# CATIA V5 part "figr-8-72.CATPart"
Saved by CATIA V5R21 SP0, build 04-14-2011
Part number: Part1
Bounding box of the stored display mesh (mm): x -81.893 to 81.893, y -175.508 to 175.508, z -50 to 146
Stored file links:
  D:\CATIA V5R21 E-RESOURCES\CATIA-V5R21\catia-v5r21-prt\c08-catia-v5r20-prt\c08-catia-v5r21-figr-8-72.CATPart
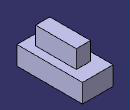
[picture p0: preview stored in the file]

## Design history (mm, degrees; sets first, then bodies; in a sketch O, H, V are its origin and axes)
Body1 (main body)
  Sketch1 on xy-plane, origin (0, 0, 0), H (1, 0, 0), V (0, 1, 0)
    line L1 (-81.8929, 175.5076) -> (81.8929, 175.5076)
    line L2 (81.8929, 175.5076) -> (81.8929, -175.5076)
    line L3 (81.8929, -175.5076) -> (-81.8929, -175.5076)
    line L4 (-81.8929, -175.5076) -> (-81.8929, 175.5076)
    axis line L5 (81.8929, -175.5076) -> (-81.8929, 175.5076)
    horizontal: L1 H, L3 H
    vertical: L2 V, L4 V
    midpoint: O L5
  Pad1: profile Sketch1, direction (0, 0, 1), length 50, mirrored extent
  Body2
    Sketch2 on xy-plane, origin (0, 0, 0), H (1, 0, 0), V (0, 1, 0)
      line L1 (-37.4906, 99.3013) -> (38.4681, 99.3013)
      line L2 (38.4681, 99.3013) -> (38.4681, -118.5305)
      line L3 (38.4681, -118.5305) -> (-37.4906, -118.5305)
      line L4 (-37.4906, -118.5305) -> (-37.4906, 99.3013)
      horizontal: L1 H, L3 H
      vertical: L2 V, L4 V
    Pad2: profile Sketch2, direction (0, 0, 1), length 146, opposite side length 150
  Trim1: tool Body2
